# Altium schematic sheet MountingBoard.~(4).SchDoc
size Legal; Organization: Altium Limited; Address1: 3 Minna Close; Address2: Belrose; Address3: NSW 2085; Address4: Australia
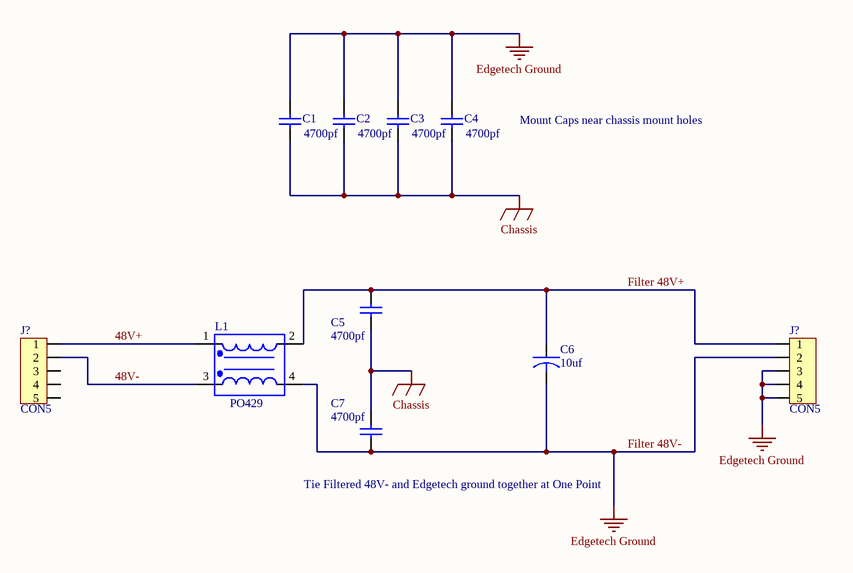
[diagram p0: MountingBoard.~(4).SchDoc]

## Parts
(Parts that share a designator on the sheet are numbered #1, #2 ... from top to bottom, then left to right.)
C1  value 4700pf  [CAPC3216L]  (hidden comment: Cap Semi)
C2  value 4700pf  [CAPC3216L]  (hidden comment: Cap Semi)
C3  value 4700pf  [CAPC3216L]  (hidden comment: Cap Semi)
C4  value 4700pf  [CAPC3216L]  (hidden comment: Cap Semi)
C5  value 4700pf  [CAPC3216L]  (hidden comment: Cap Semi)
C6  10uf  [CAPSTICK-CS4-7-SMD]
C7  value 4700pf  [CAPC3216L]  (hidden comment: Cap Semi)
J?#1  CON5  [SIP5]
J?#2  CON5  [SIP5]
L1  ManufPartNo: PO429  [Pulse_BigFoot]

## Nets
Chassis: C1.1 C2.1 C3.1 C4.1 C5.1 C7.2
Filter 48V-: C1.2 C2.2 C3.2 C4.2 C6.2 C7.1 J?#2.2 J?#2.3 J?#2.4 J?#2.5 L1.4  [also labelled Edgetech Ground]
48V+: J?#1.1 L1.1
48V-: J?#1.2 L1.3
Filter 48V+: C5.2 C6.1 J?#2.1 L1.2

Not connected (* = marked no-connect by the designer): J?#1 3 4 5

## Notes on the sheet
- Mount Caps near chassis mount holes
- (near C7) Tie Filtered 48V- and Edgetech ground together at One Point

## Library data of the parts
C1-C5 C7 = Cap Semi: Capacitor (Semiconductor SIM Model)
C6 = CAPACITOR: ManufPartNo: 106K100CS4G; Manufacturer: ITW Paktron; Vendor: Future Electronics; Value: 10
J?#1 J?#2 = CON5: Connector
L1 = COMMON MODE CHOKE: Manufacturer: Pulse Engineering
